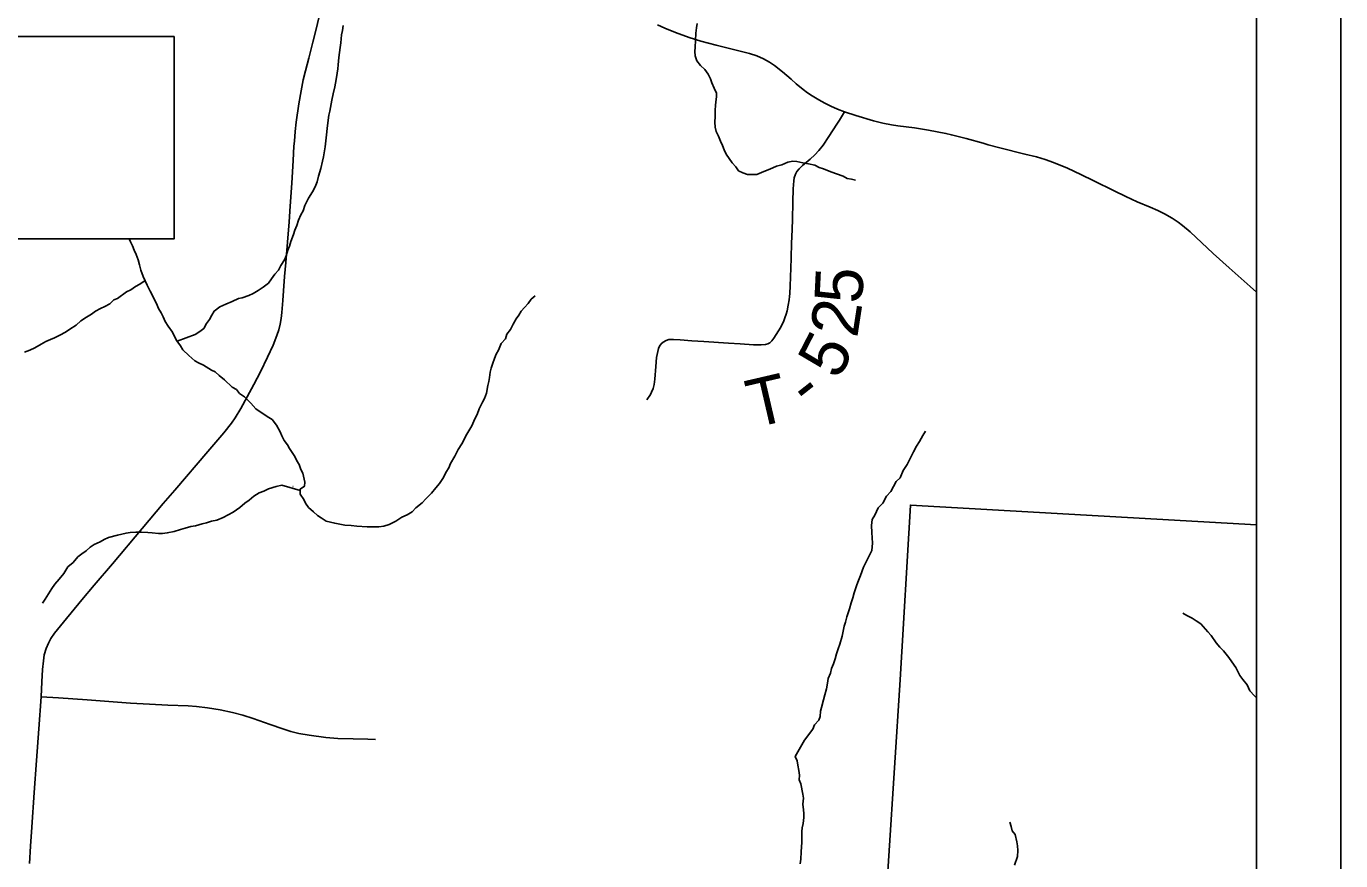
# Model space of a CAD drawing. Extents: x -8.2 to 34, y 0 to 22.
# Drawn here: x 7.441 to 9, y 17.043 to 18.032 of the extents above; entities that cross this region are included whole.
import ezdxf

# ---------------------------------------------------------------- set-up
doc = ezdxf.new("R2010")
doc.units = 0
for name, color, linetype in [('GM_X_Corporation', 7, 'Continuous'), ('GM_X_County_Road', 7, 'Continuous'), ('GM_X_Minor_River', 7, 'Continuous'), ('GM_X_Township_Road', 7, 'Continuous'), ('GM_X_Township_Road_Text', 7, 'Continuous'), ('SH_Data', 7, 'Continuous'), ('SN_P_Truss_Overhead', 7, 'Continuous')]:
    doc.layers.add(name, color=color, linetype=linetype)

msp = doc.modelspace()

# ---------------------------------------------------------------- linework, layer by layer
at = {"layer": 'GM_X_Corporation'}
msp.add_lwpolyline([(8.9, 16.3939), (8.9, 17.4413), (8.4898, 17.4646), (8.4777, 17.2575), (8.4507, 16.8404), (8.4238, 16.4247)], close=True, dxfattribs=at)
at = {"layer": 'GM_X_County_Road'}
for points in [[(7.465, 17.2948), (7.4676, 17.301), (7.4705, 17.3064), (7.4749, 17.313), (7.4854, 17.3261), (7.5074, 17.3525), (7.5221, 17.3696), (7.5437, 17.395), (7.5789, 17.4371), (7.6037, 17.4665), (7.6175, 17.4825), (7.6569, 17.5281), (7.6758, 17.5504), (7.6848, 17.5619), (7.6893, 17.5683), (7.6959, 17.5791), (7.7035, 17.593), (7.7114, 17.6078), (7.719, 17.6228), (7.7275, 17.6401), (7.734, 17.6542), (7.7386, 17.6658), (7.7408, 17.6723), (7.7425, 17.6791), (7.7436, 17.6857), (7.7444, 17.6931), (7.7458, 17.7071), (7.7465, 17.7185), (7.7478, 17.7356), (7.7491, 17.7523), (7.7512, 17.7765), (7.7533, 17.8004), (7.7545, 17.8191), (7.7562, 17.8463), (7.7577, 17.8731), (7.7588, 17.8903), (7.7593, 17.8961), (7.7602, 17.9076), (7.7614, 17.9186), (7.7645, 17.9404), (7.7672, 17.9557), (7.7698, 17.9688), (7.7725, 17.9796), (7.7764, 17.9946), (7.7813, 18.0133), (7.7852, 18.0289), (7.7883, 18.0422)], [(8.19, 18.0341), (8.1985, 18.0301), (8.2112, 18.0249), (8.2275, 18.0189), (8.2412, 18.0147), (8.2593, 18.0099), (8.2846, 18.0037), (8.299, 18.0001), (8.3078, 17.9971), (8.3156, 17.9937), (8.3226, 17.9898), (8.3287, 17.9856), (8.338, 17.9784), (8.3483, 17.9695), (8.3544, 17.9642), (8.3627, 17.9571), (8.3678, 17.9532), (8.3731, 17.9496), (8.3813, 17.9449), (8.3884, 17.9412), (8.3954, 17.9377), (8.4034, 17.9339), (8.4116, 17.9308), (8.4251, 17.9264), (8.4462, 17.9203), (8.4572, 17.9174), (8.4675, 17.9154), (8.4749, 17.9143), (8.4946, 17.9117), (8.5111, 17.9091), (8.5318, 17.9052), (8.5384, 17.9035), (8.5559, 17.8992), (8.5762, 17.8935), (8.5821, 17.8917), (8.596, 17.8881), (8.6255, 17.8808), (8.6393, 17.8773), (8.6494, 17.8744), (8.6593, 17.8708), (8.6759, 17.8639), (8.6917, 17.8564), (8.7072, 17.8489), (8.7313, 17.8373), (8.7452, 17.8305), (8.7588, 17.8243), (8.7742, 17.8178), (8.7833, 17.8138), (8.7911, 17.8101), (8.8002, 17.8049), (8.8073, 17.8002), (8.8126, 17.796), (8.8215, 17.7884), (8.8488, 17.763), (8.8678, 17.746), (8.8928, 17.7237), (8.9, 17.7171)], [(7.4453, 17.04), (7.4465, 17.0604), (7.448, 17.0829), (7.4507, 17.1242), (7.4536, 17.1619), (7.4563, 17.1993), (7.459, 17.2375), (7.46, 17.2551), (7.4607, 17.27), (7.4617, 17.28), (7.4628, 17.287), (7.465, 17.2948)]]:
    msp.add_lwpolyline(points, dxfattribs=at)
at = {"layer": 'GM_X_Minor_River'}
for points in [[(7.6203, 17.6589), (7.6418, 17.667), (7.6471, 17.6704), (7.6521, 17.6742), (7.6552, 17.6799), (7.6586, 17.6848), (7.6613, 17.6898), (7.6644, 17.6947), (7.6709, 17.6996), (7.6781, 17.703), (7.6854, 17.706), (7.693, 17.7094), (7.6976, 17.7105), (7.7052, 17.7131), (7.7105, 17.7154), (7.7162, 17.7192), (7.7224, 17.7229), (7.7285, 17.7279), (7.7323, 17.7328), (7.7361, 17.7385), (7.7403, 17.743), (7.7434, 17.7487), (7.7476, 17.7552), (7.7496, 17.7601), (7.7515, 17.7669), (7.7534, 17.7715), (7.755, 17.7772), (7.7581, 17.7856), (7.76, 17.7905), (7.7623, 17.7962), (7.7643, 17.8026), (7.767, 17.8087), (7.7696, 17.8133), (7.7716, 17.8197), (7.7762, 17.8285), (7.7808, 17.8361), (7.7839, 17.8421), (7.7862, 17.8478), (7.7878, 17.8547), (7.7905, 17.8638), (7.7928, 17.8725), (7.794, 17.8775), (7.7951, 17.8847), (7.7959, 17.8893), (7.7971, 17.8999), (7.7984, 17.9147), (7.8, 17.9269), (7.8015, 17.9318), (7.8039, 17.9448), (7.8054, 17.952), (7.8074, 17.9604), (7.8082, 17.9649), (7.8093, 17.9714), (7.8101, 17.9767), (7.8109, 17.9816), (7.8113, 17.9866), (7.8121, 17.9953), (7.8129, 18.001), (7.8137, 18.0071), (7.8145, 18.0128), (7.8153, 18.022), (7.8165, 18.0273), (7.8173, 18.033)], [(8.2368, 18.0354), (8.236, 18.0305), (8.2355, 18.024), (8.2351, 18.0153), (8.2347, 18.0076), (8.2343, 18.0023), (8.2346, 17.9974), (8.2365, 17.9913), (8.241, 17.9859), (8.246, 17.981), (8.2501, 17.9756), (8.2527, 17.9699), (8.2542, 17.9653), (8.2569, 17.9588), (8.2599, 17.9531), (8.2598, 17.9485), (8.259, 17.9428), (8.2586, 17.9383), (8.2582, 17.9329), (8.2582, 17.9253), (8.2578, 17.9185), (8.2581, 17.9128), (8.2596, 17.9074), (8.2622, 17.9021), (8.2645, 17.896), (8.2671, 17.891), (8.269, 17.8857), (8.2712, 17.8807), (8.275, 17.8754), (8.2784, 17.8704), (8.2826, 17.8655), (8.286, 17.8609), (8.2909, 17.8586), (8.2966, 17.8566), (8.3076, 17.8566), (8.316, 17.86), (8.3229, 17.863), (8.3309, 17.8664), (8.3373, 17.8682), (8.3446, 17.8712), (8.3503, 17.8723), (8.3552, 17.8719), (8.3621, 17.8704), (8.3689, 17.8692), (8.3765, 17.8676), (8.3814, 17.865), (8.3867, 17.8634), (8.3955, 17.8599), (8.4099, 17.8545), (8.4148, 17.8518), (8.4198, 17.8511), (8.4247, 17.8499)], [(7.5636, 17.7803), (7.5652, 17.7766), (7.5675, 17.7721), (7.5693, 17.7667), (7.5716, 17.7618), (7.5742, 17.7553), (7.5757, 17.7496), (7.5772, 17.7431), (7.5802, 17.7355), (7.5847, 17.7252), (7.5885, 17.7183), (7.596, 17.7038), (7.5982, 17.6977), (7.6013, 17.6924), (7.6039, 17.6878), (7.6061, 17.6824), (7.6095, 17.6767), (7.6148, 17.6698), (7.6174, 17.6637), (7.6201, 17.6592), (7.6242, 17.6534), (7.6269, 17.6489), (7.634, 17.642), (7.6412, 17.6358), (7.6458, 17.6332), (7.6515, 17.6305), (7.6609, 17.6247), (7.6655, 17.6228), (7.67, 17.6182), (7.6765, 17.6132), (7.6856, 17.6044), (7.6905, 17.6017), (7.6943, 17.5971), (7.7003, 17.5929), (7.7075, 17.5856), (7.7135, 17.5788), (7.7272, 17.5696), (7.7329, 17.5661), (7.7382, 17.5596), (7.7423, 17.5516), (7.7445, 17.5466)], [(7.5823, 17.7309), (7.576, 17.7264), (7.571, 17.7237), (7.5653, 17.7199), (7.5603, 17.7173), (7.5496, 17.7094), (7.5451, 17.7079), (7.5405, 17.7033), (7.5347, 17.6999), (7.5294, 17.6977), (7.5237, 17.6947), (7.5187, 17.6909), (7.513, 17.6875), (7.5061, 17.683), (7.5004, 17.678), (7.4931, 17.6731), (7.4878, 17.6697), (7.4813, 17.666), (7.4748, 17.6629), (7.4703, 17.6611), (7.4645, 17.6584), (7.4592, 17.6554), (7.4516, 17.6509), (7.4455, 17.6483), (7.4394, 17.646)], [(7.7445, 17.5466), (7.7472, 17.5413), (7.751, 17.5363), (7.7536, 17.5318), (7.7566, 17.5272), (7.76, 17.5222), (7.7623, 17.5173), (7.7649, 17.5127), (7.7668, 17.507), (7.7694, 17.5024), (7.7716, 17.4917), (7.7712, 17.4871), (7.7662, 17.4837), (7.7662, 17.4777), (7.7704, 17.4715), (7.7726, 17.467), (7.776, 17.462), (7.7821, 17.4566), (7.7866, 17.4524), (7.7911, 17.4494), (7.7972, 17.4455), (7.8071, 17.4432), (7.8192, 17.4409), (7.8265, 17.4404), (7.8333, 17.4396), (7.8455, 17.4388), (7.8527, 17.4388), (7.8595, 17.4391), (7.8653, 17.4399), (7.8717, 17.4417), (7.8797, 17.4455), (7.8866, 17.4504), (7.8931, 17.453), (7.8988, 17.4568), (7.9034, 17.4614), (7.911, 17.4674), (7.9153, 17.4723), (7.9221, 17.4788), (7.9271, 17.4852), (7.9313, 17.4901), (7.9363, 17.4973), (7.939, 17.5034), (7.9425, 17.5087), (7.9444, 17.514), (7.9494, 17.5228), (7.9536, 17.5307), (7.9578, 17.5372), (7.9601, 17.5417), (7.9625, 17.5467), (7.9663, 17.5527), (7.9697, 17.5588), (7.9732, 17.5668), (7.9759, 17.5721), (7.9786, 17.5786), (7.9825, 17.5865), (7.9848, 17.5911), (7.9871, 17.5972), (7.9886, 17.6063), (7.9898, 17.6112), (7.9906, 17.6158), (7.9914, 17.6223), (7.9926, 17.6268), (7.9945, 17.6329), (7.9968, 17.6386), (7.9987, 17.6435), (8.0014, 17.6485), (8.0045, 17.6561), (8.0095, 17.6617), (8.0111, 17.6671), (8.0156, 17.6727), (8.0187, 17.6792), (8.0222, 17.6853), (8.0256, 17.6898), (8.0283, 17.6944), (8.0321, 17.6989), (8.0364, 17.7035), (8.0402, 17.7088), (8.0448, 17.7129)], [(8.3634, 17.099), (8.363, 17.1036), (8.3623, 17.1101), (8.3631, 17.1173), (8.3624, 17.1222), (8.3598, 17.1344), (8.3579, 17.139), (8.3583, 17.1447), (8.3576, 17.15), (8.3561, 17.1565), (8.3554, 17.1615), (8.3531, 17.1668), (8.3643, 17.1862), (8.3742, 17.1991), (8.3762, 17.2044), (8.3811, 17.2097), (8.3827, 17.2142), (8.3831, 17.2203), (8.3843, 17.2249), (8.3866, 17.234), (8.3885, 17.2397), (8.3901, 17.2469), (8.3913, 17.2538), (8.3924, 17.2591), (8.3951, 17.2655), (8.3963, 17.2709), (8.3986, 17.2766), (8.4006, 17.2826), (8.4021, 17.2883), (8.404, 17.2944), (8.406, 17.2997), (8.4087, 17.3092), (8.4102, 17.3153), (8.4114, 17.321), (8.413, 17.326), (8.4145, 17.3324), (8.4176, 17.3419), (8.4196, 17.3488), (8.4215, 17.3548), (8.4231, 17.3605), (8.4258, 17.3689), (8.4273, 17.3734), (8.4304, 17.3814), (8.4343, 17.3913), (8.4377, 17.3981), (8.4416, 17.4061), (8.4439, 17.4107), (8.4447, 17.4194), (8.4443, 17.4259), (8.444, 17.432), (8.4437, 17.4403), (8.4445, 17.4476), (8.4475, 17.4529), (8.4514, 17.4616), (8.4571, 17.4669), (8.4614, 17.4753), (8.4667, 17.4809), (8.4729, 17.4927), (8.4775, 17.4969), (8.4813, 17.5056), (8.4859, 17.5128), (8.4936, 17.528), (8.4971, 17.5344), (8.5005, 17.5401), (8.5047, 17.5473), (8.5078, 17.5523)], [(7.7656, 17.4823), (7.7662, 17.4819), (7.7446, 17.4884), (7.7377, 17.4869), (7.7286, 17.4839), (7.7233, 17.4813), (7.7175, 17.4794), (7.7114, 17.4753), (7.7057, 17.4704), (7.7007, 17.467), (7.6946, 17.462), (7.6866, 17.4564), (7.6809, 17.453), (7.6748, 17.45), (7.6672, 17.447), (7.6611, 17.4455), (7.655, 17.4436), (7.65, 17.4425), (7.642, 17.4402), (7.6367, 17.4395), (7.6298, 17.4373), (7.6241, 17.4358), (7.6169, 17.4335), (7.6085, 17.4317), (7.6028, 17.4309), (7.5982, 17.4309), (7.5906, 17.4317), (7.5857, 17.4322), (7.5781, 17.4326), (7.5713, 17.4326), (7.5648, 17.4323), (7.5598, 17.4315), (7.5549, 17.4304), (7.5496, 17.4289), (7.5389, 17.4263), (7.5339, 17.424), (7.529, 17.421), (7.5221, 17.418), (7.5172, 17.415), (7.5126, 17.4105), (7.5072, 17.4071), (7.5026, 17.4033), (7.4969, 17.3968), (7.4908, 17.3915), (7.4858, 17.3836), (7.4804, 17.3767), (7.4751, 17.3711), (7.4716, 17.3658), (7.4678, 17.3593), (7.4639, 17.3532), (7.4605, 17.3483)], [(7.7575, 17.4868), (7.7577, 17.4867)], [(8.9, 17.2363), (8.8977, 17.2386), (8.8924, 17.2447), (8.889, 17.2516), (8.8841, 17.2581), (8.8804, 17.2627), (8.8781, 17.2673), (8.8755, 17.2722), (8.8709, 17.2787), (8.8672, 17.2841), (8.8611, 17.2921), (8.8566, 17.2963), (8.8524, 17.3016), (8.8464, 17.31), (8.8426, 17.3146), (8.8343, 17.3238), (8.8286, 17.3276), (8.8237, 17.3307), (8.8176, 17.3338), (8.8127, 17.3365)], [(8.3589, 17.0393), (8.3597, 17.045), (8.3601, 17.0538), (8.3609, 17.0652), (8.361, 17.0777), (8.3614, 17.0823), (8.3626, 17.0872), (8.3634, 17.0945), (8.3634, 17.099)], [(8.6138, 17.0742), (8.6105, 17.0787), (8.6093, 17.0837), (8.6078, 17.089)], [(8.6133, 17.038), (8.6167, 17.0483), (8.6172, 17.0551), (8.6168, 17.0608), (8.6161, 17.0654), (8.6138, 17.0742)]]:
    msp.add_lwpolyline(points, dxfattribs=at)
at = {"layer": 'GM_X_Township_Road'}
for points in [[(8.1773, 17.5894), (8.1815, 17.5956), (8.1829, 17.5984), (8.1847, 17.603), (8.1859, 17.6078), (8.1867, 17.614), (8.1878, 17.6289), (8.1888, 17.6395), (8.1902, 17.6468), (8.191, 17.6501), (8.1921, 17.6531), (8.1942, 17.6558), (8.1967, 17.658), (8.2002, 17.6599), (8.2035, 17.6609), (8.2088, 17.661), (8.2169, 17.6605), (8.2305, 17.6594), (8.2448, 17.6585), (8.2739, 17.6567), (8.2881, 17.6558), (8.3036, 17.6548), (8.3129, 17.6546), (8.3179, 17.655), (8.3208, 17.6559), (8.323, 17.6571), (8.3253, 17.6592), (8.3279, 17.6626), (8.3362, 17.6757), (8.3396, 17.683), (8.341, 17.6866), (8.3424, 17.6908), (8.3435, 17.695), (8.3449, 17.7015), (8.346, 17.7078), (8.3465, 17.7121), (8.3467, 17.7153), (8.3472, 17.7246), (8.3477, 17.735), (8.3482, 17.757), (8.3489, 17.7758), (8.349, 17.782), (8.35, 17.8028), (8.3505, 17.8241), (8.3509, 17.8395), (8.3514, 17.849), (8.3519, 17.8527), (8.3534, 17.8568), (8.3553, 17.86), (8.358, 17.8634), (8.362, 17.8673), (8.371, 17.8749), (8.3766, 17.8799), (8.3813, 17.8848), (8.3863, 17.8912), (8.3932, 17.9015), (8.4025, 17.9162), (8.4055, 17.921), (8.4116, 17.9308)], [(7.459, 17.2375), (7.4798, 17.2362), (7.4965, 17.235), (7.5138, 17.2337), (7.5343, 17.2322), (7.5652, 17.23), (7.5875, 17.2287), (7.6092, 17.2277), (7.6334, 17.2268), (7.6433, 17.226), (7.6562, 17.2244), (7.6715, 17.2219), (7.6861, 17.2188), (7.6981, 17.2156), (7.7106, 17.2117), (7.7305, 17.2048), (7.7457, 17.1994), (7.7552, 17.1965), (7.7648, 17.1941), (7.777, 17.1918), (7.7967, 17.1892), (7.8109, 17.188), (7.8289, 17.1875), (7.8463, 17.1872), (7.8557, 17.1867)]]:
    msp.add_lwpolyline(points, dxfattribs=at)
at = {"layer": 'SH_Data'}
for p, q in [((9, 21), (9, 14)), ((8.9, 20.9), (8.9, 14.1))]:
    msp.add_line(p, q, dxfattribs=at)
at = {"layer": 'SN_P_Truss_Overhead'}
msp.add_lwpolyline([(7.6168, 18.0203), (6.2543, 18.0203), (6.2543, 17.7803), (7.6168, 17.7803)], close=True, dxfattribs=at)

# ---------------------------------------------------------------- texts
at = {"layer": 'GM_X_Township_Road_Text'}
for s, rotation, p in [('5', 87.2059, (8.4325, 17.7029)), ('2', 81.2463, (8.4266, 17.6619)), ('5', 62.7035, (8.4043, 17.6118)), ('T', 13.1059, (8.3036, 17.5558)), ('-', 38.2385, (8.3693, 17.5771))]:
    msp.add_text(s, height=0.0568, rotation=rotation, dxfattribs=at).set_placement(p)

doc.saveas('drawing.dxf')
